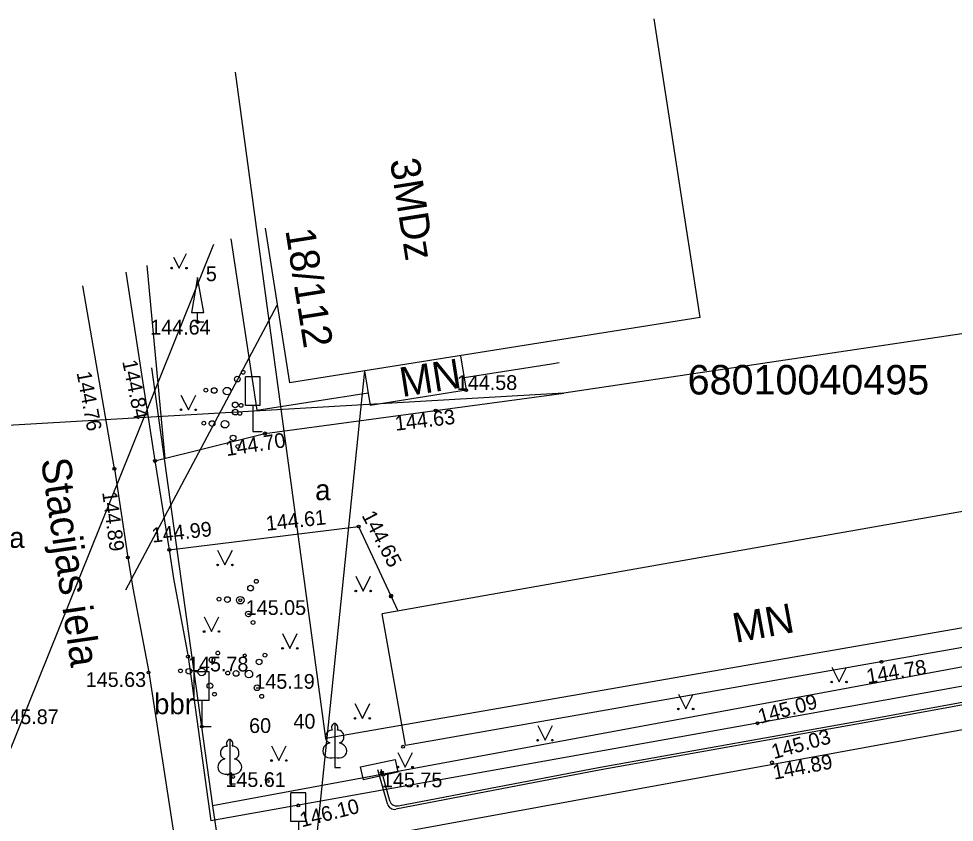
# Model space of a CAD drawing. Extents: x 728492 to 729038, y 272968 to 273171.
# Drawn here: x 728668.45 to 728700.13, y 273081.67 to 273108.91 of the extents above; entities that cross this region are included whole.
import ezdxf

# ---------------------------------------------------------------- set-up
doc = ezdxf.new("R2010")
doc.units = 0
for name, color, linetype in [('APGR_SARK_####_####_#', 7, 'Continuous'), ('BUVE_EKAS_####_####_#', 7, 'Continuous'), ('BUVE_EKAS_ADRS_TKST_#', 7, 'Continuous'), ('BUVE_EKAS_RAKS_TKST_#', 7, 'Continuous'), ('CELI_CAPM_####_####_#', 7, 'Continuous'), ('CELI_CMAL_####_####_#', 7, 'Continuous'), ('CELI_CSEG_####_TKST_#', 7, 'Continuous'), ('CELI_ELEM_####_####_#', 7, 'Continuous'), ('CELI_IELA_####_TKST_#', 7, 'Continuous'), ('ELEK_ELEM_####_####_#', 7, 'Continuous'), ('ELEK_VADP_ZSPR_####_#', 7, 'Continuous'), ('ELEK_VADP_ZSPR_####_I', 7, 'Continuous'), ('ELEK_VADV_ZSPR_####_#', 7, 'Continuous'), ('RAMI_UZMR_####_####_#', 7, 'Continuous'), ('RELJ_AATZ_####_TKST_#', 7, 'Continuous'), ('RELJ_ELEM_####_####_#', 7, 'Continuous'), ('ROBZ_KADS_####_TKST_#', 7, 'Continuous'), ('ROBZ_PROJ_####_####_#', 7, 'Continuous'), ('ROBZ_UZMR_####_####_#', 7, 'Continuous'), ('SAKT_VADV_PKAB_####_#', 7, 'Continuous'), ('SILT_ELEM_####_TKST_#', 7, 'Continuous'), ('TERT_DIAM_####_TKST_#', 7, 'Continuous'), ('TERT_ELEM_####_####_#', 7, 'Continuous'), ('TERT_KRND_####_####_#', 7, 'Continuous')]:
    doc.layers.add(name, color=color, linetype=linetype)

msp = doc.modelspace()

# ---------------------------------------------------------------- linework, layer by layer
at = {"layer": 'APGR_SARK_####_####_#'}
for points in [[(728813.011, 273107.831), (728678.847, 273084.513)], [(728678.847, 273084.513), (728675.786, 273107.093)]]:
    msp.add_lwpolyline(points, dxfattribs=at)
at = {"layer": 'BUVE_EKAS_####_####_#'}
for p, q in [((728691.529, 273098.78), (728689.965, 273108.907)), ((728676.789, 273101.809), (728677.619, 273096.563)), ((728691.529, 273098.78), (728677.619, 273096.563)), ((728686.642, 273098.001), (728686.335, 273097.952)), ((728683.41, 273097.486), (728683.596, 273096.318)), ((728680.162, 273096.968), (728680.348, 273095.8)), ((728683.596, 273096.318), (728680.348, 273095.8)), ((728705.885, 273093.165), (728689.889, 273090.35)), ((728689.889, 273090.35), (728680.757, 273088.743)), ((728681.227, 273086.074), (728680.757, 273088.743)), ((728690.777, 273085.914), (728706.669, 273088.711)), ((728681.541, 273084.289), (728681.227, 273086.074)), ((728681.541, 273084.289), (728690.777, 273085.914))]:
    msp.add_line(p, q, dxfattribs=at)
at = {"layer": 'CELI_CAPM_####_####_#'}
for points in [[(728674.775, 273080.133), (728674.775, 273080.133), (728693.992, 273083.644), (728719.252, 273088.265), (728737.995, 273091.64)], [(728672.307, 273089.605), (728672.856, 273086.761), (728673.724, 273081.115)]]:
    msp.add_lwpolyline(points, dxfattribs=at)
at = {"layer": 'CELI_CMAL_####_####_#'}
for p, q in [((728675.636, 273101.444), (728676.514, 273095.64)), ((728672.074, 273100.314), (728673.059, 273093.922)), ((728671.687, 273093.654), (728670.618, 273099.853)), ((728683.528, 273096.744), (728686.487, 273097.21)), ((728686.487, 273097.21), (728686.756, 273097.252)), ((728676.514, 273095.64), (728680.279, 273096.233)), ((728676.784, 273094.851), (728686.914, 273096.216)), ((728673.059, 273093.922), (728676.784, 273094.851)), ((728673.059, 273093.922), (728673.543, 273090.907)), ((728671.687, 273093.654), (728672.143, 273090.648)), ((728673.543, 273090.907), (728679.956, 273091.698)), ((728679.956, 273091.698), (728681.285, 273088.836)), ((728673.543, 273090.907), (728673.692, 273089.936)), ((728672.143, 273090.648), (728672.307, 273089.605)), ((728710.393, 273088.087), (728693.469, 273085.032)), ((728693.469, 273085.032), (728674.953, 273081.725))]:
    msp.add_line(p, q, dxfattribs=at)
msp.add_lwpolyline([(728673.692, 273089.936), (728674.181, 273087.286), (728674.953, 273081.725)], dxfattribs=at)
at = {"layer": 'CELI_ELEM_####_####_#'}
for p, q in [((728676.625, 273096.769), (728676.125, 273096.769)), ((728676.125, 273095.8), (728676.125, 273096.769)), ((728676.625, 273095.8), (728676.625, 273096.769)), ((728676.625, 273095.8), (728676.125, 273095.8)), ((728676.379, 273095.8), (728676.379, 273094.922)), ((728676.379, 273094.922), (728676.694, 273094.922)), ((728674.894, 273086.77), (728674.394, 273086.77)), ((728674.394, 273085.801), (728674.394, 273086.77)), ((728674.894, 273085.801), (728674.894, 273086.77)), ((728674.894, 273085.801), (728674.394, 273085.801)), ((728674.648, 273085.801), (728674.648, 273084.923)), ((728674.648, 273084.923), (728674.963, 273084.923)), ((728678.167, 273082.668), (728677.667, 273082.668)), ((728677.667, 273081.699), (728677.667, 273082.668)), ((728678.167, 273081.699), (728678.167, 273082.668)), ((728678.167, 273081.699), (728677.667, 273081.699)), ((728677.921, 273081.699), (728677.921, 273080.821))]:
    msp.add_line(p, q, dxfattribs=at)
at = {"layer": 'ELEK_ELEM_####_####_#'}
msp.add_lwpolyline([(728680.024, 273083.554), (728681.197, 273083.808), (728681.292, 273083.368), (728680.119, 273083.114)], close=True, dxfattribs=at)
at = {"layer": 'ELEK_VADP_ZSPR_####_#'}
msp.add_lwpolyline([(728672.07, 273089.548), (728677.201, 273099.2)], dxfattribs=at)
at = {"layer": 'ELEK_VADP_ZSPR_####_I'}
for points in [[(728681.295, 273082.233), (728688.088, 273083.536), (728697.444, 273085.206), (728707.979, 273087.132), (728712.349, 273087.981)], [(728712.579, 273087.924), (728707.997, 273087.034), (728697.462, 273085.108), (728688.106, 273083.438), (728681.224, 273082.117)], [(728680.936, 273082.295), (728680.61, 273083.447)], [(728680.706, 273083.475), (728681.007, 273082.41)]]:
    msp.add_lwpolyline(points, dxfattribs=at)
for centre in [(728681.177, 273082.363), (728681.248, 273082.478)]:
    msp.add_arc(centre, 0.25, 195.7972, 280.86, dxfattribs=at)
at = {"layer": 'ELEK_VADV_ZSPR_####_#'}
msp.add_line((728666.081, 273078.979), (728675.06, 273101.261), dxfattribs=at)
at = {"layer": 'RAMI_UZMR_####_####_#'}
msp.add_lwpolyline([(728726.814, 273102.175), (728686.914, 273096.216), (728659.323, 273094.615), (728619.629, 273079.414), (728545.121, 273067.256)], dxfattribs=at)
at = {"layer": 'RELJ_ELEM_####_####_#'}
for centre in [(728674.507, 273098.631), (728683.596, 273096.318), (728682.565, 273095.63), (728676.784, 273094.851), (728676.784, 273094.851), (728671.687, 273093.654), (728671.687, 273093.654), (728673.059, 273093.922), (728679.956, 273091.698), (728679.956, 273091.698), (728673.543, 273090.907), (728673.543, 273090.907), (728672.143, 273090.648), (728672.143, 273090.648), (728675.949, 273089.201), (728675.949, 273089.201), (728681.054, 273089.333), (728681.061, 273089.357), (728674.181, 273087.286), (728676.104, 273087.329), (728697.663, 273087.112), (728672.842, 273086.753), (728674.648, 273084.923), (728693.469, 273085.032), (728681.466, 273084.235), (728693.955, 273083.702), (728675.707, 273083.213), (728680.749, 273083.361), (728676.882, 273083.071), (728677.913, 273082.246)]:
    msp.add_circle(centre, 0.05, dxfattribs=at)
at = {"layer": 'ROBZ_PROJ_####_####_#'}
msp.add_line((728672.947, 273097.072), (728675.015, 273082.231), dxfattribs=at)
at = {"layer": 'ROBZ_UZMR_####_####_#'}
for p, q in [((728707.448, 273088.246), (728675.015, 273082.231)), ((728675.015, 273082.231), (728677.033, 273068.656))]:
    msp.add_line(p, q, dxfattribs=at)
at = {"layer": 'SAKT_VADV_PKAB_####_#'}
for p, q in [((728680.162, 273096.968), (728678.992, 273085.631)), ((728678.992, 273085.631), (728677.472, 273070.914))]:
    msp.add_line(p, q, dxfattribs=at)
at = {"layer": 'TERT_ELEM_####_####_#'}
for p, q in [((728673.878, 273100.453), (728674.128, 273100.953)), ((728673.691, 273100.827), (728673.878, 273100.453)), ((728674.507, 273098.631), (728674.507, 273098.951)), ((728674.507, 273098.631), (728674.717, 273098.631)), ((728673.942, 273096.154), (728674.192, 273095.654)), ((728674.192, 273095.654), (728674.442, 273096.154)), ((728675.183, 273090.897), (728675.433, 273090.397)), ((728675.433, 273090.397), (728675.683, 273090.897)), ((728679.864, 273090.011), (728680.114, 273089.511)), ((728680.114, 273089.511), (728680.364, 273090.011)), ((728674.727, 273088.64), (728674.977, 273088.14)), ((728674.977, 273088.14), (728675.227, 273088.64)), ((728677.381, 273088.068), (728677.631, 273087.568)), ((728677.631, 273087.568), (728677.881, 273088.068)), ((728695.983, 273086.929), (728696.233, 273086.429)), ((728696.233, 273086.429), (728696.483, 273086.929)), ((728690.789, 273086.014), (728691.039, 273085.514)), ((728691.039, 273085.514), (728691.289, 273086.014)), ((728679.835, 273085.697), (728680.085, 273085.197)), ((728680.085, 273085.197), (728680.335, 273085.697)), ((728686.023, 273084.957), (728686.273, 273084.457)), ((728686.273, 273084.457), (728686.523, 273084.957)), ((728677.01, 273084.269), (728677.26, 273083.769)), ((728677.26, 273083.769), (728677.51, 273084.269)), ((728679.149, 273083.873), (728679.149, 273083.526)), ((728681.285, 273084.043), (728681.535, 273083.543)), ((728681.535, 273083.543), (728681.785, 273084.043)), ((728679.149, 273083.526), (728679.349, 273083.526)), ((728675.592, 273083.328), (728675.592, 273082.981)), ((728675.592, 273082.981), (728675.792, 273082.981))]:
    msp.add_line(p, q, dxfattribs=at)
msp.add_lwpolyline([(728674.297, 273098.951), (728674.717, 273098.951), (728674.507, 273100.131)], close=True, dxfattribs=at)
for points in [[(728679.149, 273085.026), (728679.149, 273083.873)], [(728679.239, 273084.794), (728679.238, 273084.795)], [(728675.592, 273084.481), (728675.592, 273083.328)], [(728675.682, 273084.249), (728675.681, 273084.25)]]:
    msp.add_lwpolyline(points, dxfattribs=at)
for centre, radius in [((728673.628, 273100.453), 0.028), ((728674.128, 273100.453), 0.0263), ((728676.046, 273096.925), 0.064), ((728675.85, 273096.694), 0.096), ((728674.784, 273096.32), 0.064), ((728675.068, 273096.307), 0.096), ((728675.502, 273096.286), 0.128), ((728675.778, 273095.819), 0.096), ((728673.942, 273095.653), 0.028), ((728674.442, 273095.653), 0.0263), ((728675.78, 273095.573), 0.096), ((728675.936, 273095.53), 0.064), ((728675.976, 273095.804), 0.064), ((728674.714, 273095.199), 0.064), ((728674.998, 273095.186), 0.096), ((728675.432, 273095.165), 0.128), ((728675.708, 273094.698), 0.096), ((728675.866, 273094.409), 0.064), ((728675.183, 273090.396), 0.028), ((728675.683, 273090.396), 0.0263), ((728676.493, 273089.84), 0.064), ((728676.297, 273089.609), 0.096), ((728679.864, 273089.511), 0.028), ((728680.364, 273089.511), 0.0263), ((728675.231, 273089.235), 0.064), ((728675.515, 273089.222), 0.096), ((728675.949, 273089.201), 0.128), ((728676.225, 273088.734), 0.096), ((728676.383, 273088.445), 0.064), ((728674.726, 273088.139), 0.028), ((728675.226, 273088.139), 0.0263), ((728675.188, 273087.409), 0.064), ((728676.786, 273087.338), 0.064), ((728677.381, 273087.568), 0.028), ((728677.881, 273087.568), 0.0263), ((728674.992, 273087.178), 0.096), ((728676.59, 273087.107), 0.096), ((728673.926, 273086.804), 0.064), ((728674.21, 273086.791), 0.096), ((728674.644, 273086.77), 0.128), ((728675.524, 273086.733), 0.064), ((728675.808, 273086.72), 0.096), ((728676.242, 273086.699), 0.128), ((728674.92, 273086.303), 0.096), ((728695.983, 273086.428), 0.028), ((728696.483, 273086.428), 0.0263), ((728675.078, 273086.014), 0.064), ((728676.518, 273086.232), 0.096), ((728676.676, 273085.943), 0.064), ((728690.789, 273085.514), 0.028), ((728691.289, 273085.514), 0.0263), ((728679.835, 273085.197), 0.028), ((728680.335, 273085.197), 0.0263), ((728686.022, 273084.457), 0.028), ((728686.522, 273084.457), 0.0263), ((728677.01, 273083.768), 0.028), ((728677.51, 273083.768), 0.0263), ((728681.285, 273083.543), 0.028), ((728681.785, 273083.543), 0.0263)]:
    msp.add_circle(centre, radius, dxfattribs=at)
for centre, major_axis, ratio, start_param, end_param in [((728679.021, 273084.581), (-0.039, -0.212), 0.861323, 3.141593, 6.283185), ((728679.149, 273084.876), (0, -0.15), 0.707107, 3.14537, 5.287485), ((728679.149, 273084.876), (0, -0.15), 0.707107, 0.995701, 3.137816), ((728679.277, 273084.581), (0.039, -0.212), 0.861323, 0, 3.141593), ((728675.592, 273084.331), (0, -0.15), 0.707107, 3.14537, 5.287485), ((728675.592, 273084.331), (0, -0.15), 0.707107, 0.995701, 3.137816), ((728675.464, 273084.036), (-0.039, -0.212), 0.861323, 3.141593, 6.283185), ((728675.72, 273084.036), (0.039, -0.212), 0.861323, 0, 3.141593), ((728679.059, 273084.119), (0.307, 0.095), 0.814445, 1.570796, 4.752015), ((728679.239, 273084.119), (-0.307, 0.095), 0.814445, 1.531171, 4.712389), ((728675.502, 273083.574), (0.307, 0.095), 0.814445, 1.570796, 4.752015), ((728675.682, 273083.574), (-0.307, 0.095), 0.814445, 1.531171, 4.712389)]:
    msp.add_ellipse(centre, major_axis=major_axis, ratio=ratio, start_param=start_param, end_param=end_param, dxfattribs=at)
at = {"layer": 'TERT_KRND_####_####_#'}
msp.add_lwpolyline([(728673.402, 273094.006), (728672.794, 273100.543)], dxfattribs=at)

# ---------------------------------------------------------------- texts
at = {"layer": 'BUVE_EKAS_ADRS_TKST_#'}
msp.add_text('18/112', height=1, rotation=278.9941, dxfattribs=at).set_placement((728677.474, 273101.741))
at = {"layer": 'BUVE_EKAS_RAKS_TKST_#'}
for s, rotation, p in [('3MDz', 278.9941, (728681.015, 273104.107)), ('MN', 9.0546, (728681.43, 273096.083)), ('MN', 10.404, (728692.724, 273087.752))]:
    msp.add_text(s, height=1, rotation=rotation, dxfattribs=at).set_placement(p)
at = {"layer": 'CELI_CSEG_####_TKST_#'}
for s, p in [('a', (728678.486, 273092.59)), ('a', (728668.123, 273090.974)), ('bbr', (728673.029, 273085.337))]:
    msp.add_text(s, height=0.7, dxfattribs=at).set_placement(p)
at = {"layer": 'CELI_IELA_####_TKST_#'}
msp.add_text('Stacijas iela', height=1, rotation=278.2327, dxfattribs=at).set_placement((728669.197, 273093.962))
at = {"layer": 'RELJ_AATZ_####_TKST_#'}
for s, p in [(' 144.64', (728672.715, 273098.202)), (' 144.58', (728683.099, 273096.325)), (' 145.05', (728675.949, 273088.701)), ('145.78', (728674.181, 273086.786)), ('145.63', (728670.716, 273086.261)), (' 145.19', (728676.242, 273086.199)), (' 145.61', (728675.26, 273082.872)), ('145.75', (728680.749, 273082.861))]:
    msp.add_text(s, height=0.5, dxfattribs=at).set_placement(p)
for s, rotation, p in [(' 144.84', 281.7574, (728671.912, 273097.476)), (' 144.76', 280.4685, (728670.371, 273097.094)), (' 144.63', 6.6886, (728681.032, 273094.919)), (' 144.70', 8.6576, (728675.306, 273094.054)), (' 144.89', 277.3568, (728671.25, 273093.043)), (' 144.61', 6.2252, (728676.657, 273091.532)), (' 144.65', 297.7505, (728679.964, 273092.238)), (' 144.99', 6.2935, (728672.792, 273091.131)), (' 144.78', 9.4045, (728697.018, 273086.339)), ('145.09', 15.3182, (728693.563, 273085.009)), ('145.03', 15.605, (728694.021, 273083.811)), ('144.89', 10.8773, (728694.034, 273083.117)), ('146.10', 14.1646, (728678.035, 273081.502))]:
    msp.add_text(s, height=0.5, rotation=rotation, dxfattribs=at).set_placement(p)
at = {"layer": 'ROBZ_KADS_####_TKST_#'}
msp.add_text('68010040495', height=1, dxfattribs=at).set_placement((728691.103, 273096.172))
at = {"layer": 'SILT_ELEM_####_TKST_#'}
msp.add_text('145.87', height=0.5, dxfattribs=at).set_placement((728667.756, 273085.002))
at = {"layer": 'TERT_DIAM_####_TKST_#'}
for s, p in [('5', (728674.785, 273100.014)), ('60', (728676.25, 273084.701)), ('40', (728677.751, 273084.847))]:
    msp.add_text(s, height=0.5, dxfattribs=at).set_placement(p)

doc.saveas('drawing.dxf')
